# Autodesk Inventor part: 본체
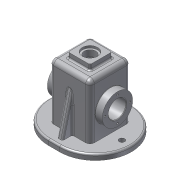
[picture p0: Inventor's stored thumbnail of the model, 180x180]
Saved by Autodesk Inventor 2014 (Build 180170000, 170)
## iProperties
Created: 2017-07
Part Number: 본체
Material: 알루미늄 6061
Document SubType Name: Modeling
Designer: user
Mass: 983.368 g
Surface Area: 989.873 cm^2
Volume: 362.867 cm^3
Density: 2.71 g/cm^3
Appearance: 알루미늄 - 평지
Author: user
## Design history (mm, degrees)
sketch "스케치1"
  geometry: L1 (0, 0)-(74, 0); L2 (74, 0)-(74, 110); L3 (74, 110)-(0, 110); L4 (0, 110)-(0, 0)
  constraints: 8 end point, 2 parallel, 1 horizontal, 1 perpendicular
  dimensions: "d0" = 74 distance of L2.end L3.end; "d1" = 110 distance of L1.end L2.end
extrude "돌출1" new body sketch "스케치1" stored distance "d2" = 74; taper "d3" = 0 deg
node "작업 평면1"
sketch "스케치3"
  geometry: L1 (-112, 65)-(38, 65); L2 (38, 65)-(38, -65); L3 (38, -65)-(-112, -65); L4 (-112, -65)-(-112, 65); L5 (0, 37)-(-74, 37) reference; 4 further points
  constraints: 8 end point, 3 midpoint, 2 parallel, 1 horizontal, 1 horizontal alignment, 1 perpendicular, 1 vertical alignment
  dimensions: "d5" = 150 distance of L1.start L1.end; "d6" = 130 distance of L1.end L2.end
extrude "돌출2" join sketch "스케치3" distance "d7" = 10; taper "d8" = 0 deg
sketch "스케치4"
  geometry: L1 (0, 110)-(74, 110) reference; L2 (0, 10)-(0, 110) reference; L3 (74, 110)-(74, 10) reference; L4 (67, 0)-(67, 105); L5 (67, 105)-(7, 105); L6 (7, 105)-(7, 0); L7 (-38, 0)-(112, 0) reference; L8 (7, 0)-(67, 0); 1 further point
  constraints: 8 end point, 2 point on line, 1 collinear
  dimensions: "d9" = 7 distance between parallel lines of L3 L4; "d122" = 5 distance between parallel lines of L1 L5
extrude "돌출4" cut sketch "스케치4" stored distance "d12" = 64; taper "d13" = 0 deg
sketch "스케치5"
  geometry: L1 (74, 110)-(74, 10) reference; L2 (5.906, 55)-(74, 55); L3 (87, 55)-(87, 82.5); L4 (87, 82.5)-(74, 82.5); L5 (60, 68.5)-(74, 82.5); L6 (60, 68.5)-(60, 55); L7 (87, 55)-(74, 55); L8 (-13, 82.5)-(-13, 55); L9 (5.906, 55)-(-13, 55); L10 (7, 0)-(7, 105) reference; L11 (67, 105)-(67, 0) reference; L12 (-38, 0)-(112, 0) reference; L13 (-13, 82.5)-(0, 82.5); L14 (0, 82.5)-(14, 68.5); L15 (14, 55)-(14, 68.5); 3 further points
  constraints: 22 end point, 7 perpendicular, 4 point on line, 2 midpoint, 1 parallel
  dimensions: "d17" = 13 distance between parallel lines of L1 L3; "d18" = 100 distance between parallel lines of L3 L8; "d20" = 7 distance between parallel lines of L11 L6; "d22" = 55 diameter of L4 L7; "d23" = 55 distance between parallel lines of L12 L9; "d25" = 135 deg angle of L11 L5; "d27" = 68.09363 distance from line of L2.start L1; "d95" = 135 deg angle of L10 L14 (derived); "d96" = 55 diameter of L13 L2; "d97" = 7 distance between parallel lines of L10 L15; "d98" = 20.85965 distance from line of L12.end L14
revolve "회전1" sketch "스케치5" stored, may be unused: angle "d28" = 90 deg
sketch "스케치6"
  geometry: L1 (17, 57)-(57, 57); L2 (57, 57)-(57, 17); L3 (57, 17)-(17, 17); L4 (17, 17)-(17, 57); L5 (17, 57)-(57, 17); L6 (57, 57)-(17, 17); L7 (112, -28)-(-38, -28) reference; L8 (112, 102)-(112, -28) reference; 2 further points
  constraints: 12 end point, 2 midpoint, 2 parallel, 1 horizontal, 1 perpendicular
  dimensions: "d29" = 65 distance from line of L7 point (37, 37); "d30" = 75 distance from line of L8 point (37, 37); "d31" = 40 distance of L1.end L2.end; "d32" = 40 distance of L2.end L3.end
extrude "돌출5" join sketch "스케치6" distance "d33" = 10; taper "d34" = 0 deg
fillet "모깎기1" dims "d35" = 8
fillet "모깎기3" dims "d37" = 3
fillet "모깎기4" dims "d38" = 3
sketch "스케치7"
  geometry: L1 (54, 57)-(20, 57) reference; L2 (17, 54)-(17, 20) reference; L3 (20, 17)-(54, 17) reference; L4 (57, 20)-(57, 54) reference; L5 (17, 37)-(57, 37); L6 (37, 57)-(37, 17); 4 further points
  constraints: 5 midpoint, 4 end point, 2 coincident
hole "구멍1" sketch "스케치7" at (37, 37) diameter "d39" = 21; stored, may be unused: countersink angle "d43" = 90 deg, drill point angle "d45" = 118 deg; dims "d40" = 6, "d41" = 28, "d42" = 4, "d44" = 8
node "작업 평면3"
  node "작업 평면2"
sketch "스케치8"
  geometry: L1 (10, 37)-(110, 37) reference; L2 (110, -37)-(10, -37) reference; L3 (82.194, -37)-(10, -55); L4 (6.545, -65)-(55.596, -65); L5 (82.194, -37)-(10, -37); 2 further points
  constraints: 6 end point, 1 collinear, 1 point on line
  dimensions: "d49" = 14 deg angle of L4 L3; "d61" = 10 distance of point (10, -65) L3.end
fillet "모깎기5"
fillet "모깎기6"
feature "리브1" dims "d62" = 1, "d63" = 10, "d64" = 0, "d65" = 0, "d66" = 1, "d67" = 1
fillet "모깎기8" dims "d69" = 3
sketch "스케치9" dims "d70" = 45
  geometry: C1 r 27.5 at (0, 0) reference; 3 further points
  constraints: 1 coincident, 1 vertical alignment, 2 other
hole "구멍3" sketch "스케치9" at (0, 22.5) diameter "d71" = 3.242; stored, may be unused: countersink angle "d75" = 90 deg, drill point angle "d77" = 118 deg; dims "d72" = 8, "d73" = 28, "d74" = 4, "d76" = 10
fillet "모깎기10" dims "d82" = 0.5
fillet "모깎기11" dims "d83" = 0.5
fillet "모깎기12" dims "d84" = 3
fillet "모깎기13" dims "d85" = 3
sketch "스케치10"
  geometry: L1 (-46, 110)-(-12, 110) reference; L2 (8, 0)-(8, 100) reference; 2 further points
  constraints: 1 other
  dimensions: "d87" = 30 distance from line of L1 point (-29, 80); "d88" = 37 distance from line of L2 point (-29, 80)
fillet "모깎기15" dims "d89" = 8
feature "엠보싱1" dims "d90" = 0.5, "d91" = 0
hole "구멍4" diameter "d101" = 32; stored, may be unused: countersink angle "d105" = 90 deg, drill point angle "d107" = 0 deg; dims "d99" = 10, "d100" = 10, "d102" = 6, "d103" = 4, "d104" = 2, "d106" = 8
chamfer "모따기1" distance "d108" = 1; stored, may be unused: second distance "d109" = 2, angle "d110" = 45 deg
sketch "스케치11"
  geometry: L1 (47, -62)-(27, -62) reference; L2 (27, 62)-(47, 62) reference; L3 (37, 62)-(37, -62); L4 (-35, 0)-(109, 0); L5 (95, 18.716)-(95, -18.716); L6 (-21, 18.716)-(-21, -18.716); A1 r 62 centre (47, 0) between (47, -62) and (47, 62) reference; A2 r 62 centre (27, 0) between (27, 62) and (27, -62) reference; 3 further points
  constraints: 8 end point, 4 midpoint, 2 point on circle, 2 symmetric about line, 1 perpendicular
  dimensions: "d114" = 58 distance between parallel lines of L3 L5
hole "구멍5" sketch "스케치11" at (95, 0), (-21, 0) diameter "d115" = 10; stored, may be unused: countersink angle "d119" = 90 deg, drill point angle "d121" = 0 deg; dims "d116" = 6, "d117" = 4, "d118" = 2, "d120" = 8
fillet "모깎기16" dims "d123" = 3
fillet "모깎기17" dims "d124" = 3
fillet "모깎기18" dims "d125" = 0.5
node "솔리드1"
mirror "대칭2"
pattern_circular "원형 패턴2" dims angle "d112" = 360 deg
mirror "대칭4"
other parameters: "d46" = -13
